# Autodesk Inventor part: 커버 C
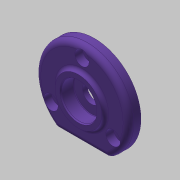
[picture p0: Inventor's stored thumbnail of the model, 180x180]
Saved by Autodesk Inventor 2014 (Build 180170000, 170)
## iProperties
Created: 2020-04
Part Number: 커버 C
Material: 알루미늄 6061
Document SubType Name: Modeling
Designer: mduedu
Density: 2.71 g/cm^3
Appearance: Violet
Mass: 35.2376 g
Surface Area: 62.3739 cm^2
Volume: 13.0028 cm^3
Author: mduedu
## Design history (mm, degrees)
sketch "스케치1"
  geometry: C1 r 26 at (0, 0); 1 further point
  constraints: 1 centre point, 1 coincident
  dimensions: "d0" = 52 diameter of C1
extrude "돌출1" new body sketch "스케치1" distance "d1" = 7; taper "d2" = 0 deg
sketch "스케치2"
  geometry: L1 (-14.62, -21.5)-(14.62, -21.5); A1 r 26 centre (0, 0) between (-14.62, -21.5) and (14.62, -21.5) reference; 1 further point
  constraints: 2 end point, 2 point on circle, 1 horizontal
  dimensions: "d3" = 21.5 distance from line of L1 point (0, 0)
extrude "돌출2" cut sketch "스케치2" stored distance "d4" = 7; taper "d5" = 0 deg
sketch "스케치6"
  geometry: C1 r 13 at (0, 0); 1 further point
  constraints: 1 centre point, 1 coincident
  dimensions: "d29" = 26 diameter of C1
extrude "돌출5" join sketch "스케치6" distance "d30" = 2; taper "d31" = 0 deg
fillet "모깎기1" dims "d6" = 3
fillet "모깎기2" dims "d7" = 3
fillet "모깎기4" dims "d33" = 2
sketch "스케치3" dims "d8" = 40
  geometry: 3 further points
  constraints: 2 vertical alignment, 1 coincident, 2 other
hole "구멍1" sketch "스케치3" at (0, 20) diameter "d9" = 4.5; stored, may be unused: countersink angle "d13" = 90 deg, drill point angle "d15" = 118 deg; dims "d10" = 6, "d11" = 8, "d12" = 4.4, "d14" = 8
sketch "스케치4"
  geometry: C1 r 14 at (0, 0); 1 further point
  constraints: 1 centre point, 1 coincident
  dimensions: "d19" = 28 diameter of C1
extrude "돌출3" join sketch "스케치4" distance "d20" = 4; taper "d21" = 0 deg
sketch "스케치5"
  geometry: C1 r 12 at (0, 0); 1 further point
  constraints: 1 centre point, 1 coincident
  dimensions: "d22" = 24 diameter of C1
extrude "돌출4" cut sketch "스케치5" distance "d23" = 3; taper "d24" = 0 deg
fillet "모깎기3" dims "d25" = 3
chamfer "모따기1" distance "d26" = 0.5; stored, may be unused: second distance "d27" = 2, angle "d28" = 45 deg
sketch "스케치7"
  geometry: 2 further points
  constraints: 1 coincident
hole "구멍2" sketch "스케치7" at (0, 0) diameter "d34" = 10; stored, may be unused: countersink angle "d38" = 90 deg, drill point angle "d40" = 118 deg; dims "d35" = 6, "d36" = 20, "d37" = 7.3, "d39" = 8
fillet "모깎기5" dims "d41" = 0.3
chamfer "모따기2" distance "d42" = 0.7; stored, may be unused: second distance "d43" = 2, angle "d44" = 30 deg
node "솔리드1"
pattern_circular "원형 패턴1" dims angle "d17" = 360 deg
node "투영된 루프1"
